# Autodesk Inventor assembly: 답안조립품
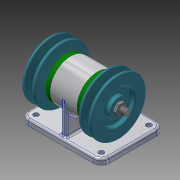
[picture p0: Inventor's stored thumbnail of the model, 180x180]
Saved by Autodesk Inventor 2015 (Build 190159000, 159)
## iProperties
Created: 2019-09
Part Number: 답안조립품
Document SubType Name: Assembly
Designer: Lineart
Author: Lineart
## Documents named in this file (10)
- C:\Users\Lineart\Desktop\490904V1039\답안조립품.iam
- C:\Users\Lineart\Desktop\490904V1039\본체.ipt
- C:\Users\Lineart\Desktop\490904V1039\베어링 6004.ipt
- C:\Users\Lineart\Desktop\490904V1039\축.ipt
- C:\Users\Lineart\Desktop\490904V1039\커버.ipt
- C:\Users\Lineart\Desktop\490904V1039\오일 실 17 30 5.ipt
- C:\Users\Lineart\Desktop\490904V1039\키 5 x 5 x 12.ipt
- C:\Users\Lineart\Desktop\490904V1039\V-벨트풀리.ipt
- C:\Users\Lineart\Desktop\490904V1039\너트 M10x1.ipt
- C:\Users\Lineart\Desktop\490904V1039\볼트 M4.ipt
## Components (2 placed, 1 different names)
1. V-벨트풀리:1
2. V-벨트풀리:2
